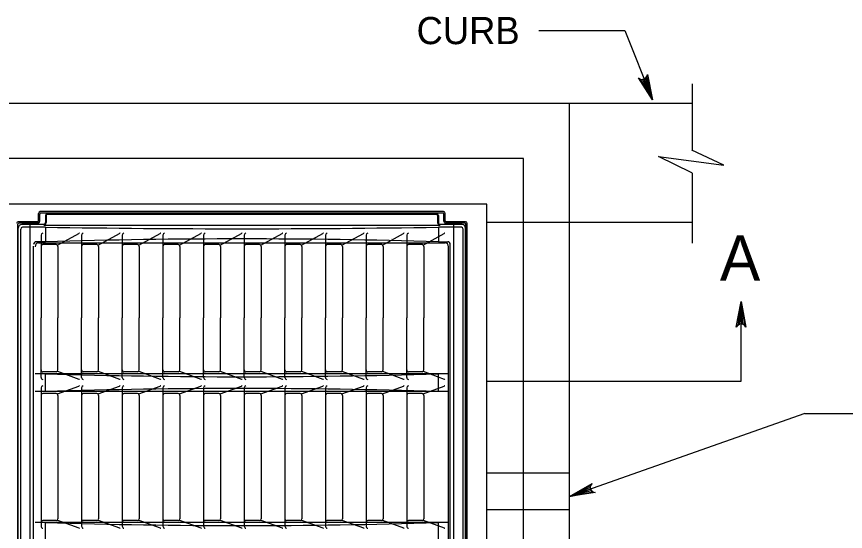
# Model space of a CAD drawing. Extents: x 6.91 to 13.84, y 0.35 to 9.99.
# Drawn here: x 8.644 to 10.473, y 8.799 to 9.934 of the extents above; entities that cross this region are included whole.
import ezdxf

# ---------------------------------------------------------------- set-up
doc = ezdxf.new("R2010")
doc.units = 0
for name, color, linetype in [('DETL-DIMS', 7, 'Continuous'), ('DETL-LINE', 7, 'Continuous'), ('DETL-NOTE', 7, 'Continuous'), ('DETL-TITL', 7, 'Continuous')]:
    doc.layers.add(name, color=color, linetype=linetype)

msp = doc.modelspace()

# ---------------------------------------------------------------- linework, layer by layer
at = {"layer": 'DETL-DIMS'}
for p, q in [((9.7962, 9.9036), (9.9858, 9.9036)), ((9.9858, 9.9036), (10.0469, 9.7506)), ((10.2426, 9.1301), (10.2426, 9.3062)), ((9.682, 9.1301), (10.2426, 9.1301)), ((10.3833, 9.0591), (9.864, 8.8754)), ((10.3833, 9.0591), (10.4987, 9.0591))]:
    msp.add_line(p, q, dxfattribs=at)
for points in [[(10.0469, 9.7506), (10.0161, 9.7992), (10.0205, 9.7962), (10.0249, 9.7956), (10.0286, 9.7964), (10.0319, 9.7984), (10.0346, 9.8019), (10.0358, 9.807), (10.0469, 9.7506), (10.0346, 9.8019), (10.0319, 9.7984), (10.0469, 9.7506), (10.0286, 9.7964), (10.0249, 9.7956), (10.0469, 9.7506), (10.0205, 9.7962)], [(10.2426, 9.3062), (10.2533, 9.2496), (10.2502, 9.254), (10.2464, 9.2562), (10.2426, 9.2569), (10.2389, 9.2562), (10.2351, 9.254), (10.232, 9.2496), (10.2426, 9.3062), (10.2351, 9.254), (10.2389, 9.2562), (10.2426, 9.3062), (10.2426, 9.2569), (10.2464, 9.2562), (10.2426, 9.3062), (10.2502, 9.254)], [(9.864, 8.8754), (9.9138, 8.9042), (9.9107, 8.8999), (9.9099, 8.8956), (9.9105, 8.8918), (9.9124, 8.8885), (9.9158, 8.8856), (9.9209, 8.8843), (9.864, 8.8754), (9.9158, 8.8856), (9.9124, 8.8885), (9.864, 8.8754), (9.9105, 8.8918), (9.9099, 8.8956), (9.864, 8.8754), (9.9107, 8.8999)]]:
    msp.add_lwpolyline(points, dxfattribs=at)
at = {"layer": 'DETL-LINE'}
for p, q in [((10.1347, 9.7858), (10.1347, 9.6399)), ((10.1347, 9.7427), (7.2076, 9.7427)), ((9.864, 8.1996), (9.864, 9.7427)), ((9.7629, 9.6214), (7.4976, 9.6214)), ((9.7629, 9.4798), (9.7629, 9.6214)), ((10.1347, 9.5898), (10.1347, 9.4343)), ((9.682, 9.5203), (7.5785, 9.5203)), ((9.682, 8.4019), (9.682, 9.5203)), ((8.6929, 9.484), (8.6929, 9.4999)), ((8.6957, 9.4829), (8.6957, 9.4989)), ((9.586, 9.5042), (8.6966, 9.5042)), ((9.5851, 9.501), (8.6975, 9.501)), ((8.7096, 9.4956), (8.7096, 9.4803)), ((9.5711, 9.4979), (8.7115, 9.4979)), ((9.5731, 9.4956), (9.5731, 9.4803)), ((9.587, 9.4829), (9.587, 9.4989)), ((9.5898, 9.484), (9.5898, 9.4999)), ((8.6471, 8.4514), (8.6471, 9.4765)), ((8.691, 9.4819), (8.648, 9.4819)), ((8.6919, 9.4787), (8.6489, 9.4787)), ((8.6742, 9.476), (8.6742, 9.4787)), ((8.6742, 8.4495), (8.6742, 9.476)), ((9.5786, 9.4739), (8.7048, 9.4739)), ((9.6337, 9.4787), (9.5907, 9.4787)), ((9.6346, 9.4819), (9.5916, 9.4819)), ((9.6085, 9.476), (9.6085, 9.4787)), ((9.6085, 8.4495), (9.6085, 9.476)), ((9.6356, 8.4514), (9.6356, 9.4765)), ((9.6384, 8.4504), (9.6384, 9.4776)), ((10.1347, 9.4798), (9.682, 9.4798)), ((9.7629, 8.3007), (9.7629, 9.4798)), ((8.6533, 8.4599), (8.6533, 9.4656)), ((8.7078, 9.4699), (8.6571, 9.4699)), ((8.7078, 9.4699), (8.7078, 9.4377)), ((9.6256, 9.4699), (9.5748, 9.4699)), ((9.5748, 9.4699), (9.5748, 9.4377)), ((9.6293, 8.4599), (9.6293, 9.4656)), ((8.7078, 9.4377), (8.6874, 9.4377)), ((8.6929, 9.4353), (9.5898, 9.4353)), ((9.5748, 9.4377), (9.5953, 9.4377)), ((8.6818, 8.4942), (8.6818, 9.4278)), ((9.5972, 8.4988), (9.5972, 9.4267)), ((9.6009, 8.4942), (9.6009, 9.4313)), ((9.5972, 9.1463), (8.6854, 9.1463)), ((8.7078, 9.1074), (8.7078, 9.1463)), ((9.5748, 9.1074), (9.5748, 9.1463)), ((9.5972, 9.1074), (8.6854, 9.1074)), ((9.682, 8.9277), (9.864, 8.9277)), ((9.682, 8.8468), (9.864, 8.8468)), ((9.5972, 8.8181), (8.6854, 8.8181)), ((8.7078, 8.7791), (8.7078, 8.8181)), ((9.5748, 8.7791), (9.5748, 8.8181))]:
    msp.add_line(p, q, dxfattribs=at)
msp.add_lwpolyline([(10.1341, 9.5898), (10.0604, 9.6259), (10.2047, 9.6063), (10.1341, 9.6399)], dxfattribs=at)
for centre, major_axis, start_param, end_param in [((8.6966, 9.4999), (0, 0.0043), 0, 1.570796), ((8.6975, 9.4989), (0, 0.00215), 0, 1.570796), ((8.7115, 9.4956), (0, 0.00227), 0, 1.570796), ((9.5711, 9.4956), (0, 0.00227), 4.712389, 6.283185), ((9.5851, 9.4989), (0, 0.00215), 4.712389, 6.283185), ((9.586, 9.4999), (0, 0.0043), 4.712389, 6.283185), ((8.648, 9.4776), (0, 0.0043), 0, 1.570796), ((8.6489, 9.4765), (0, 0.00215), 0, 1.570796), ((8.691, 9.484), (0, 0.00215), 3.141593, 4.712389), ((8.6919, 9.4829), (0, 0.0043), 3.141593, 4.712389), ((8.7041, 9.4803), (0, 0.00632), 3.141593, 4.712389), ((9.5786, 9.4803), (0, 0.00632), 1.570796, 3.141593), ((9.5907, 9.4829), (0, 0.0043), 1.570796, 3.141593), ((9.5916, 9.484), (0, 0.00215), 1.570796, 3.141593), ((9.6337, 9.4765), (0, 0.00215), 4.712389, 6.283185), ((9.6346, 9.4776), (0, 0.0043), 4.712389, 6.283185), ((8.6571, 9.4656), (0, 0.0043), 0, 1.570796), ((9.1413, 45.6115), (0, 36.1451), 3.1278, 3.155386), ((9.6256, 9.4656), (0, 0.0043), 4.712389, 6.283185), ((8.6874, 9.4313), (0, 0.00645), 0, 1.570796), ((8.6929, 9.4267), (0, 0.0086), 0, 1.570796), ((9.1413, -10.7224), (0, 20.1663), 6.258462, 6.307909), ((9.5898, 9.4267), (0, 0.0086), 4.712389, 6.283185), ((9.5953, 9.4313), (0, 0.00645), 4.712389, 6.283185), ((9.1413, 28.4196), (0, 19.2797), 3.115732, 3.167453), ((9.1413, -10.1659), (0, 19.2797), 6.257325, 6.309046), ((9.1413, 28.0913), (0, 19.2797), 3.115732, 3.167453)]:
    msp.add_ellipse(centre, major_axis=major_axis, ratio=0.869565, start_param=start_param, end_param=end_param, dxfattribs=at)
at = {"layer": 'DETL-NOTE'}
for p, q in [((8.7078, 9.4956), (8.7078, 9.4803)), ((8.7115, 9.4999), (9.5711, 9.4999)), ((9.5748, 9.4956), (9.5748, 9.4803)), ((8.7041, 9.476), (8.6555, 9.476)), ((8.7078, 9.4846), (8.7078, 9.4804)), ((9.6271, 9.476), (9.5786, 9.476)), ((8.648, 8.4581), (8.648, 9.4674)), ((8.7343, 9.4302), (8.7814, 9.4562)), ((8.824, 9.4302), (8.8711, 9.4562)), ((8.9137, 9.4302), (8.9608, 9.4562)), ((9.0034, 9.4302), (9.0505, 9.4562)), ((9.0931, 9.4302), (9.1402, 9.4562)), ((9.1828, 9.4302), (9.2299, 9.4562)), ((9.2725, 9.4302), (9.3196, 9.4562)), ((9.3621, 9.4302), (9.4093, 9.4562)), ((9.4518, 9.4302), (9.4976, 9.4562)), ((9.5415, 9.4302), (9.5873, 9.4562)), ((9.6346, 8.4581), (9.6346, 9.4674)), ((8.6984, 9.4523), (8.6984, 9.2697)), ((8.7877, 9.4523), (8.7877, 9.2697)), ((8.8774, 9.4523), (8.8774, 9.2697)), ((8.967, 9.4523), (8.967, 9.2697)), ((9.0567, 9.4523), (9.0567, 9.2697)), ((9.1464, 9.4523), (9.1464, 9.2697)), ((9.2361, 9.4523), (9.2361, 9.2697)), ((9.3258, 9.4523), (9.3258, 9.2697)), ((9.4155, 9.4523), (9.4155, 9.2697)), ((9.4711, 9.4459), (9.4711, 9.4459)), ((9.5052, 9.4523), (9.5052, 9.2697)), ((8.7317, 9.4314), (8.7022, 9.4314)), ((8.7354, 9.4271), (8.7354, 9.2697)), ((8.8214, 9.4314), (8.7914, 9.4314)), ((8.8251, 9.4271), (8.8251, 9.2697)), ((8.9111, 9.4314), (8.8811, 9.4314)), ((8.9148, 9.4271), (8.9148, 9.2697)), ((9.0007, 9.4314), (8.9708, 9.4314)), ((9.0045, 9.4271), (9.0045, 9.2697)), ((9.0904, 9.4314), (9.0605, 9.4314)), ((9.0942, 9.4271), (9.0942, 9.2697)), ((9.1801, 9.4314), (9.1502, 9.4314)), ((9.1839, 9.4271), (9.1839, 9.2697)), ((9.2698, 9.4314), (9.2399, 9.4314)), ((9.2736, 9.4271), (9.2736, 9.2697)), ((9.3595, 9.4314), (9.3295, 9.4314)), ((9.3632, 9.4271), (9.3632, 9.2697)), ((9.4492, 9.4314), (9.4192, 9.4314)), ((9.4529, 9.4271), (9.4529, 9.2697)), ((9.5389, 9.4314), (9.5089, 9.4314)), ((9.5426, 9.4271), (9.5426, 9.2697)), ((8.6984, 9.1384), (8.6984, 9.2697)), ((8.7354, 9.1549), (8.7354, 9.2697)), ((8.7877, 9.1384), (8.7877, 9.2697)), ((8.8251, 9.1549), (8.8251, 9.2697)), ((8.8774, 9.1384), (8.8774, 9.2697)), ((8.9148, 9.1549), (8.9148, 9.2697)), ((8.967, 9.1384), (8.967, 9.2697)), ((9.0045, 9.1549), (9.0045, 9.2697)), ((9.0567, 9.1384), (9.0567, 9.2697)), ((9.0942, 9.1549), (9.0942, 9.2697)), ((9.1464, 9.1384), (9.1464, 9.2697)), ((9.1839, 9.1549), (9.1839, 9.2697)), ((9.2361, 9.1384), (9.2361, 9.2697)), ((9.2736, 9.1549), (9.2736, 9.2697)), ((9.3258, 9.1384), (9.3258, 9.2697)), ((9.3632, 9.1549), (9.3632, 9.2697)), ((9.4155, 9.1384), (9.4155, 9.2697)), ((9.4529, 9.1549), (9.4529, 9.2697)), ((9.5052, 9.1384), (9.5052, 9.2697)), ((9.5426, 9.1549), (9.5426, 9.2697)), ((8.7317, 9.1506), (8.7022, 9.1506)), ((8.7343, 9.1519), (8.7814, 9.1345)), ((8.8214, 9.1506), (8.7914, 9.1506)), ((8.824, 9.1519), (8.8711, 9.1345)), ((8.9111, 9.1506), (8.8811, 9.1506)), ((8.9137, 9.1519), (8.9608, 9.1345)), ((9.0007, 9.1506), (8.9708, 9.1506)), ((9.0034, 9.1519), (9.0505, 9.1345)), ((9.0904, 9.1506), (9.0605, 9.1506)), ((9.0931, 9.1519), (9.1402, 9.1345)), ((9.1801, 9.1506), (9.1502, 9.1506)), ((9.1828, 9.1519), (9.2299, 9.1345)), ((9.2698, 9.1506), (9.2399, 9.1506)), ((9.2725, 9.1519), (9.3196, 9.1345)), ((9.3595, 9.1506), (9.3295, 9.1506)), ((9.3621, 9.1519), (9.4093, 9.1345)), ((9.4492, 9.1506), (9.4192, 9.1506)), ((9.4518, 9.1519), (9.4976, 9.1345)), ((9.5389, 9.1506), (9.5089, 9.1506)), ((9.5415, 9.1519), (9.5873, 9.1345)), ((8.6984, 9.1153), (8.6984, 8.8101)), ((8.7343, 9.1018), (8.7814, 9.1192)), ((8.7877, 9.1153), (8.7877, 8.8101)), ((8.824, 9.1018), (8.8711, 9.1192)), ((8.8774, 9.1153), (8.8774, 8.8101)), ((8.9137, 9.1018), (8.9608, 9.1192)), ((8.967, 9.1153), (8.967, 8.8101)), ((9.0034, 9.1018), (9.0505, 9.1192)), ((9.0567, 9.1153), (9.0567, 8.8101)), ((9.0931, 9.1018), (9.1402, 9.1192)), ((9.1464, 9.1153), (9.1464, 8.8101)), ((9.1828, 9.1018), (9.2299, 9.1192)), ((9.2361, 9.1153), (9.2361, 8.8101)), ((9.2725, 9.1018), (9.3196, 9.1192)), ((9.3258, 9.1153), (9.3258, 8.8101)), ((9.3621, 9.1018), (9.4093, 9.1192)), ((9.4155, 9.1153), (9.4155, 8.8101)), ((9.4518, 9.1018), (9.4976, 9.1192)), ((9.5052, 9.1153), (9.5052, 8.8101)), ((9.5415, 9.1018), (9.5873, 9.1192)), ((8.7317, 9.1031), (8.7022, 9.1031)), ((8.7354, 9.0988), (8.7354, 8.8267)), ((8.8214, 9.1031), (8.7914, 9.1031)), ((8.8251, 9.0988), (8.8251, 8.8267)), ((8.9111, 9.1031), (8.8811, 9.1031)), ((8.9148, 9.0988), (8.9148, 8.8267)), ((9.0007, 9.1031), (8.9708, 9.1031)), ((9.0045, 9.0988), (9.0045, 8.8267)), ((9.0904, 9.1031), (9.0605, 9.1031)), ((9.0942, 9.0988), (9.0942, 8.8267)), ((9.1801, 9.1031), (9.1502, 9.1031)), ((9.1839, 9.0988), (9.1839, 8.8267)), ((9.2698, 9.1031), (9.2399, 9.1031)), ((9.2736, 9.0988), (9.2736, 8.8267)), ((9.3595, 9.1031), (9.3295, 9.1031)), ((9.3632, 9.0988), (9.3632, 8.8267)), ((9.4492, 9.1031), (9.4192, 9.1031)), ((9.4529, 9.0988), (9.4529, 8.8267)), ((9.5389, 9.1031), (9.5089, 9.1031)), ((9.5426, 9.0988), (9.5426, 8.8267)), ((8.7317, 8.8224), (8.7022, 8.8224)), ((8.7343, 8.8237), (8.7814, 8.8063)), ((8.8214, 8.8224), (8.7914, 8.8224)), ((8.824, 8.8237), (8.8711, 8.8063)), ((8.9111, 8.8224), (8.8811, 8.8224)), ((8.9137, 8.8237), (8.9608, 8.8063)), ((9.0007, 8.8224), (8.9708, 8.8224)), ((9.0034, 8.8237), (9.0505, 8.8063)), ((9.0904, 8.8224), (9.0605, 8.8224)), ((9.0931, 8.8237), (9.1402, 8.8063)), ((9.1801, 8.8224), (9.1502, 8.8224)), ((9.1828, 8.8237), (9.2299, 8.8063)), ((9.2698, 8.8224), (9.2399, 8.8224)), ((9.2725, 8.8237), (9.3196, 8.8063)), ((9.3595, 8.8224), (9.3295, 8.8224)), ((9.3621, 8.8237), (9.4093, 8.8063)), ((9.4492, 8.8224), (9.4192, 8.8224)), ((9.4518, 8.8237), (9.4976, 8.8063)), ((9.5389, 8.8224), (9.5089, 8.8224)), ((9.5415, 8.8237), (9.5873, 8.8063))]:
    msp.add_line(p, q, dxfattribs=at)
for centre, major_axis, start_param, end_param in [((8.7115, 9.4956), (0, 0.0043), 0, 1.570796), ((9.5711, 9.4956), (0, 0.0043), 4.712389, 6.283185), ((8.6555, 9.4674), (0, 0.0086), 0, 1.570796), ((8.7041, 9.4803), (0, 0.0043), 3.141593, 4.712389), ((9.5786, 9.4803), (0, 0.0043), 1.570796, 3.141593), ((9.6271, 9.4674), (0, 0.0086), 4.712389, 6.283185), ((8.7022, 9.4523), (0, 0.0043), 0, 1.570796), ((8.7831, 9.4523), (0, 0.0043), 0, 0.447297), ((8.7914, 9.4523), (0, 0.0043), 0, 1.570796), ((8.8728, 9.4523), (0, 0.0043), 0, 0.447297), ((8.8811, 9.4523), (0, 0.0043), 0, 1.570796), ((8.9624, 9.4523), (0, 0.0043), 0, 0.447297), ((8.9708, 9.4523), (0, 0.0043), 0, 1.570796), ((9.0521, 9.4523), (0, 0.0043), 0, 0.447297), ((9.0605, 9.4523), (0, 0.0043), 0, 1.570796), ((9.1418, 9.4523), (0, 0.0043), 0, 0.447297), ((9.1502, 9.4523), (0, 0.0043), 0, 1.570796), ((9.2315, 9.4523), (0, 0.0043), 0, 0.447297), ((9.2399, 9.4523), (0, 0.0043), 0, 1.570796), ((9.3212, 9.4523), (0, 0.0043), 0, 0.447297), ((9.3295, 9.4523), (0, 0.0043), 0, 1.570796), ((9.4109, 9.4523), (0, 0.0043), 0, 0.447297), ((9.4192, 9.4523), (0, 0.0043), 0, 1.570796), ((9.4992, 9.4523), (0, 0.0043), 0, 0.447297), ((9.5089, 9.4523), (0, 0.0043), 0, 1.570796), ((9.5889, 9.4523), (0, 0.0043), 0, 0.447297), ((8.7022, 9.4271), (0, 0.0043), 0, 1.570796), ((8.7317, 9.4271), (0, 0.0043), 4.712389, 6.283185), ((8.7914, 9.4271), (0, 0.0043), 0, 1.570796), ((8.8214, 9.4271), (0, 0.0043), 4.712389, 6.283185), ((8.8811, 9.4271), (0, 0.0043), 0, 1.570796), ((8.9111, 9.4271), (0, 0.0043), 4.712389, 6.283185), ((8.9708, 9.4271), (0, 0.0043), 0, 1.570796), ((9.0007, 9.4271), (0, 0.0043), 4.712389, 6.283185), ((9.0605, 9.4271), (0, 0.0043), 0, 1.570796), ((9.0904, 9.4271), (0, 0.0043), 4.712389, 6.283185), ((9.1502, 9.4271), (0, 0.0043), 0, 1.570796), ((9.1801, 9.4271), (0, 0.0043), 4.712389, 6.283185), ((9.2399, 9.4271), (0, 0.0043), 0, 1.570796), ((9.2698, 9.4271), (0, 0.0043), 4.712389, 6.283185), ((9.3295, 9.4271), (0, 0.0043), 0, 1.570796), ((9.3595, 9.4271), (0, 0.0043), 4.712389, 6.283185), ((9.4192, 9.4271), (0, 0.0043), 0, 1.570796), ((9.4492, 9.4271), (0, 0.0043), 4.712389, 6.283185), ((9.5089, 9.4271), (0, 0.0043), 0, 1.570796), ((9.5389, 9.4271), (0, 0.0043), 4.712389, 6.283185), ((8.7022, 9.1549), (0, 0.0043), 1.570796, 3.141593), ((8.7317, 9.1549), (0, 0.0043), 3.141593, 4.712389), ((8.7914, 9.1549), (0, 0.0043), 1.570796, 3.141593), ((8.8214, 9.1549), (0, 0.0043), 3.141593, 4.712389), ((8.8811, 9.1549), (0, 0.0043), 1.570796, 3.141593), ((8.9111, 9.1549), (0, 0.0043), 3.141593, 4.712389), ((8.9708, 9.1549), (0, 0.0043), 1.570796, 3.141593), ((9.0007, 9.1549), (0, 0.0043), 3.141593, 4.712389), ((9.0605, 9.1549), (0, 0.0043), 1.570796, 3.141593), ((9.0904, 9.1549), (0, 0.0043), 3.141593, 4.712389), ((9.1502, 9.1549), (0, 0.0043), 1.570796, 3.141593), ((9.1801, 9.1549), (0, 0.0043), 3.141593, 4.712389), ((9.2399, 9.1549), (0, 0.0043), 1.570796, 3.141593), ((9.2698, 9.1549), (0, 0.0043), 3.141593, 4.712389), ((9.3295, 9.1549), (0, 0.0043), 1.570796, 3.141593), ((9.3595, 9.1549), (0, 0.0043), 3.141593, 4.712389), ((9.4192, 9.1549), (0, 0.0043), 1.570796, 3.141593), ((9.4492, 9.1549), (0, 0.0043), 3.141593, 4.712389), ((9.5089, 9.1549), (0, 0.0043), 1.570796, 3.141593), ((9.5389, 9.1549), (0, 0.0043), 3.141593, 4.712389), ((8.7022, 9.1384), (0, 0.0043), 1.570796, 3.141593), ((8.7831, 9.1384), (0, 0.0043), 2.694296, 3.141593), ((8.7914, 9.1384), (0, 0.0043), 1.570796, 3.141593), ((8.8728, 9.1384), (0, 0.0043), 2.694296, 3.141593), ((8.8811, 9.1384), (0, 0.0043), 1.570796, 3.141593), ((8.9624, 9.1384), (0, 0.0043), 2.694296, 3.141593), ((8.9708, 9.1384), (0, 0.0043), 1.570796, 3.141593), ((9.0521, 9.1384), (0, 0.0043), 2.694296, 3.141593), ((9.0605, 9.1384), (0, 0.0043), 1.570796, 3.141593), ((9.1418, 9.1384), (0, 0.0043), 2.694296, 3.141593), ((9.1502, 9.1384), (0, 0.0043), 1.570796, 3.141593), ((9.2315, 9.1384), (0, 0.0043), 2.694296, 3.141593), ((9.2399, 9.1384), (0, 0.0043), 1.570796, 3.141593), ((9.3212, 9.1384), (0, 0.0043), 2.694296, 3.141593), ((9.3295, 9.1384), (0, 0.0043), 1.570796, 3.141593), ((9.4109, 9.1384), (0, 0.0043), 2.694296, 3.141593), ((9.4192, 9.1384), (0, 0.0043), 1.570796, 3.141593), ((9.4992, 9.1384), (0, 0.0043), 2.694296, 3.141593), ((9.5089, 9.1384), (0, 0.0043), 1.570796, 3.141593), ((9.5889, 9.1384), (0, 0.0043), 2.694296, 3.141593), ((8.7022, 9.1153), (0, 0.0043), 0, 1.570796), ((8.7831, 9.1153), (0, 0.0043), 0, 0.447297), ((8.7914, 9.1153), (0, 0.0043), 0, 1.570796), ((8.8728, 9.1153), (0, 0.0043), 0, 0.447297), ((8.8811, 9.1153), (0, 0.0043), 0, 1.570796), ((8.9624, 9.1153), (0, 0.0043), 0, 0.447297), ((8.9708, 9.1153), (0, 0.0043), 0, 1.570796), ((9.0521, 9.1153), (0, 0.0043), 0, 0.447297), ((9.0605, 9.1153), (0, 0.0043), 0, 1.570796), ((9.1418, 9.1153), (0, 0.0043), 0, 0.447297), ((9.1502, 9.1153), (0, 0.0043), 0, 1.570796), ((9.2315, 9.1153), (0, 0.0043), 0, 0.447297), ((9.2399, 9.1153), (0, 0.0043), 0, 1.570796), ((9.3212, 9.1153), (0, 0.0043), 0, 0.447297), ((9.3295, 9.1153), (0, 0.0043), 0, 1.570796), ((9.4109, 9.1153), (0, 0.0043), 0, 0.447297), ((9.4192, 9.1153), (0, 0.0043), 0, 1.570796), ((9.4992, 9.1153), (0, 0.0043), 0, 0.447297), ((9.5089, 9.1153), (0, 0.0043), 0, 1.570796), ((9.5889, 9.1153), (0, 0.0043), 0, 0.447297), ((8.7022, 9.0988), (0, 0.0043), 0, 1.570796), ((8.7317, 9.0988), (0, 0.0043), 4.712389, 6.283185), ((8.7914, 9.0988), (0, 0.0043), 0, 1.570796), ((8.8214, 9.0988), (0, 0.0043), 4.712389, 6.283185), ((8.8811, 9.0988), (0, 0.0043), 0, 1.570796), ((8.9111, 9.0988), (0, 0.0043), 4.712389, 6.283185), ((8.9708, 9.0988), (0, 0.0043), 0, 1.570796), ((9.0007, 9.0988), (0, 0.0043), 4.712389, 6.283185), ((9.0605, 9.0988), (0, 0.0043), 0, 1.570796), ((9.0904, 9.0988), (0, 0.0043), 4.712389, 6.283185), ((9.1502, 9.0988), (0, 0.0043), 0, 1.570796), ((9.1801, 9.0988), (0, 0.0043), 4.712389, 6.283185), ((9.2399, 9.0988), (0, 0.0043), 0, 1.570796), ((9.2698, 9.0988), (0, 0.0043), 4.712389, 6.283185), ((9.3295, 9.0988), (0, 0.0043), 0, 1.570796), ((9.3595, 9.0988), (0, 0.0043), 4.712389, 6.283185), ((9.4192, 9.0988), (0, 0.0043), 0, 1.570796), ((9.4492, 9.0988), (0, 0.0043), 4.712389, 6.283185), ((9.5089, 9.0988), (0, 0.0043), 0, 1.570796), ((9.5389, 9.0988), (0, 0.0043), 4.712389, 6.283185), ((8.7022, 8.8267), (0, 0.0043), 1.570796, 3.141593), ((8.7317, 8.8267), (0, 0.0043), 3.141593, 4.712389), ((8.7914, 8.8267), (0, 0.0043), 1.570796, 3.141593), ((8.8214, 8.8267), (0, 0.0043), 3.141593, 4.712389), ((8.8811, 8.8267), (0, 0.0043), 1.570796, 3.141593), ((8.9111, 8.8267), (0, 0.0043), 3.141593, 4.712389), ((8.9708, 8.8267), (0, 0.0043), 1.570796, 3.141593), ((9.0007, 8.8267), (0, 0.0043), 3.141593, 4.712389), ((9.0605, 8.8267), (0, 0.0043), 1.570796, 3.141593), ((9.0904, 8.8267), (0, 0.0043), 3.141593, 4.712389), ((9.1502, 8.8267), (0, 0.0043), 1.570796, 3.141593), ((9.1801, 8.8267), (0, 0.0043), 3.141593, 4.712389), ((9.2399, 8.8267), (0, 0.0043), 1.570796, 3.141593), ((9.2698, 8.8267), (0, 0.0043), 3.141593, 4.712389), ((9.3295, 8.8267), (0, 0.0043), 1.570796, 3.141593), ((9.3595, 8.8267), (0, 0.0043), 3.141593, 4.712389), ((9.4192, 8.8267), (0, 0.0043), 1.570796, 3.141593), ((9.4492, 8.8267), (0, 0.0043), 3.141593, 4.712389), ((9.5089, 8.8267), (0, 0.0043), 1.570796, 3.141593), ((9.5389, 8.8267), (0, 0.0043), 3.141593, 4.712389), ((8.7022, 8.8101), (0, 0.0043), 1.570796, 3.141593), ((8.7831, 8.8101), (0, 0.0043), 2.694296, 3.141593), ((8.7914, 8.8101), (0, 0.0043), 1.570796, 3.141593), ((8.8728, 8.8101), (0, 0.0043), 2.694296, 3.141593), ((8.8811, 8.8101), (0, 0.0043), 1.570796, 3.141593), ((8.9624, 8.8101), (0, 0.0043), 2.694296, 3.141593), ((8.9708, 8.8101), (0, 0.0043), 1.570796, 3.141593), ((9.0521, 8.8101), (0, 0.0043), 2.694296, 3.141593), ((9.0605, 8.8101), (0, 0.0043), 1.570796, 3.141593), ((9.1418, 8.8101), (0, 0.0043), 2.694296, 3.141593), ((9.1502, 8.8101), (0, 0.0043), 1.570796, 3.141593), ((9.2315, 8.8101), (0, 0.0043), 2.694296, 3.141593), ((9.2399, 8.8101), (0, 0.0043), 1.570796, 3.141593), ((9.3212, 8.8101), (0, 0.0043), 2.694296, 3.141593), ((9.3295, 8.8101), (0, 0.0043), 1.570796, 3.141593), ((9.4109, 8.8101), (0, 0.0043), 2.694296, 3.141593), ((9.4192, 8.8101), (0, 0.0043), 1.570796, 3.141593), ((9.4992, 8.8101), (0, 0.0043), 2.694296, 3.141593), ((9.5089, 8.8101), (0, 0.0043), 1.570796, 3.141593), ((9.5889, 8.8101), (0, 0.0043), 2.694296, 3.141593)]:
    msp.add_ellipse(centre, major_axis=major_axis, ratio=0.869565, start_param=start_param, end_param=end_param, dxfattribs=at)

# ---------------------------------------------------------------- texts
msp.add_text('CURB', height=0.06, dxfattribs=at).set_placement((9.5267, 9.8736))
at = {"layer": 'DETL-TITL'}
msp.add_text('A', height=0.1, dxfattribs=at).set_placement((10.1957, 9.3517))

doc.saveas('drawing.dxf')
